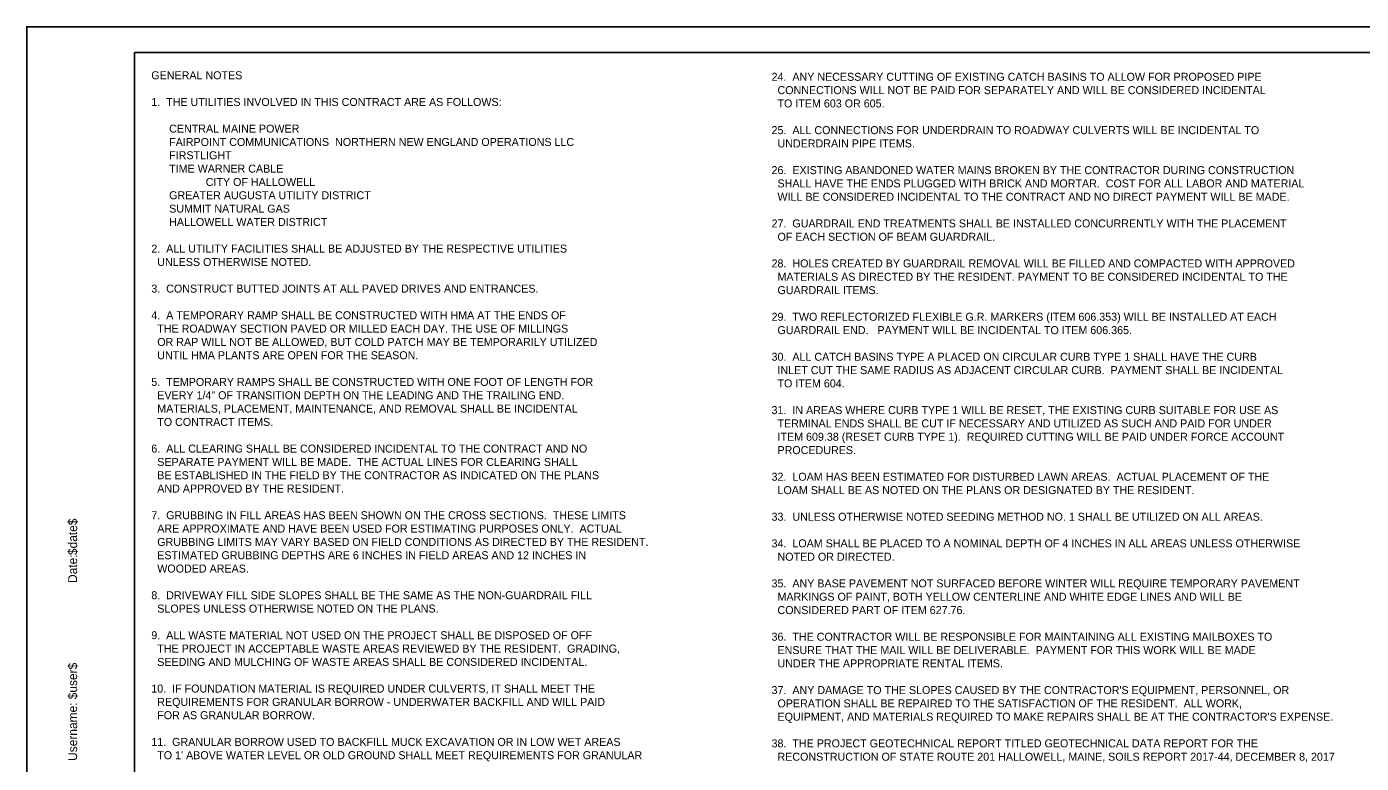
# Model space of a CAD drawing. Extents: x -0.13 to 2.7, y -0.05 to 1.78.
# Drawn here: x -0.135 to 1.533, y 0.861 to 1.782 of the extents above; entities that cross this region are included whole.
import ezdxf

# ---------------------------------------------------------------- set-up
doc = ezdxf.new("R2010")
doc.units = 0
for name, color, linetype in [('ANNOTATION', 7, 'Continuous'), ('BORDER', 7, 'Continuous'), ('PLOT BOUNDARY', 7, 'Continuous')]:
    doc.layers.add(name, color=color, linetype=linetype)

msp = doc.modelspace()

# ---------------------------------------------------------------- linework, layer by layer
at = {"layer": 'BORDER'}
for p, q in [((2.6553, 1.75), (0, 1.75)), ((0, 1.75), (0, 0))]:
    msp.add_line(p, q, dxfattribs=at)
at = {"layer": 'PLOT BOUNDARY'}
msp.add_lwpolyline([(-0.1349, -0.051), (2.6984, -0.051), (2.6984, 1.7823), (-0.1349, 1.7823)], close=True, dxfattribs=at)

# ---------------------------------------------------------------- texts
at = {"layer": 'ANNOTATION'}
for s, p in [('GENERAL NOTES', (0.0208, 1.7166)), ('24.  ANY NECESSARY CUTTING OF EXISTING CATCH BASINS TO ALLOW FOR PROPOSED PIPE ', (0.7957, 1.7147)), ('  CONNECTIONS WILL NOT BE PAID FOR SEPARATELY AND WILL BE CONSIDERED INCIDENTAL ', (0.7957, 1.698)), ('1.  THE UTILITIES INVOLVED IN THIS CONTRACT ARE AS FOLLOWS: ', (0.0208, 1.6832)), ('  TO ITEM 603 OR 605.', (0.7957, 1.6814)), ('      CENTRAL MAINE POWER', (0.0208, 1.6499)), ('25.  ALL CONNECTIONS FOR UNDERDRAIN TO ROADWAY CULVERTS WILL BE INCIDENTAL TO ', (0.7957, 1.648)), ('      FAIRPOINT COMMUNICATIONS  NORTHERN NEW ENGLAND OPERATIONS LLC', (0.0208, 1.6332)), ('  UNDERDRAIN PIPE ITEMS.', (0.7957, 1.6314)), ('      FIRSTLIGHT', (0.0208, 1.6166)), ('      TIME WARNER CABLE', (0.0208, 1.5999)), ('26.  EXISTING ABANDONED WATER MAINS BROKEN BY THE CONTRACTOR DURING CONSTRUCTION ', (0.7957, 1.598)), ('CITY OF HALLOWELL', (0.0888, 1.5832)), ('  SHALL HAVE THE ENDS PLUGGED WITH BRICK AND MORTAR.  COST FOR ALL LABOR AND MATERIAL ', (0.7957, 1.5814)), ('      GREATER AUGUSTA UTILITY DISTRICT', (0.0208, 1.5666)), ('  WILL BE CONSIDERED INCIDENTAL TO THE CONTRACT AND NO DIRECT PAYMENT WILL BE MADE.', (0.7957, 1.5647)), ('      SUMMIT NATURAL GAS', (0.0208, 1.5499)), ('      HALLOWELL WATER DISTRICT', (0.0208, 1.5332)), ('27.  GUARDRAIL END TREATMENTS SHALL BE INSTALLED CONCURRENTLY WITH THE PLACEMENT ', (0.7957, 1.5314)), ('  OF EACH SECTION OF BEAM GUARDRAIL.', (0.7957, 1.5147)), ('2.  ALL UTILITY FACILITIES SHALL BE ADJUSTED BY THE RESPECTIVE UTILITIES ', (0.0208, 1.4999)), ('  UNLESS OTHERWISE NOTED.', (0.0208, 1.4832)), ('28.  HOLES CREATED BY GUARDRAIL REMOVAL WILL BE FILLED AND COMPACTED WITH APPROVED ', (0.7957, 1.4814)), ('  MATERIALS AS DIRECTED BY THE RESIDENT. PAYMENT TO BE CONSIDERED INCIDENTAL TO THE ', (0.7957, 1.4647)), ('3.  CONSTRUCT BUTTED JOINTS AT ALL PAVED DRIVES AND ENTRANCES.', (0.0208, 1.4499)), ('  GUARDRAIL ITEMS.', (0.7957, 1.448)), ('4.  A TEMPORARY RAMP SHALL BE CONSTRUCTED WITH HMA AT THE ENDS OF ', (0.0208, 1.4166)), ('29.  TWO REFLECTORIZED FLEXIBLE G.R. MARKERS (ITEM 606.353) WILL BE INSTALLED AT EACH ', (0.7957, 1.4147)), ('  THE ROADWAY SECTION PAVED OR MILLED EACH DAY. THE USE OF MILLINGS ', (0.0208, 1.3999)), ('  GUARDRAIL END.   PAYMENT WILL BE INCIDENTAL TO ITEM 606.365.', (0.7957, 1.398)), ('  OR RAP WILL NOT BE ALLOWED, BUT COLD PATCH MAY BE TEMPORARILY UTILIZED ', (0.0208, 1.3832)), ('  UNTIL HMA PLANTS ARE OPEN FOR THE SEASON.', (0.0208, 1.3666)), ('30.  ALL CATCH BASINS TYPE A PLACED ON CIRCULAR CURB TYPE 1 SHALL HAVE THE CURB ', (0.7957, 1.3647)), ('  INLET CUT THE SAME RADIUS AS ADJACENT CIRCULAR CURB.  PAYMENT SHALL BE INCIDENTAL ', (0.7957, 1.348)), ('5.  TEMPORARY RAMPS SHALL BE CONSTRUCTED WITH ONE FOOT OF LENGTH FOR ', (0.0208, 1.3332)), ('  TO ITEM 604.', (0.7957, 1.3314)), ('  EVERY 1/4" OF TRANSITION DEPTH ON THE LEADING AND THE TRAILING END. ', (0.0208, 1.3166)), ('  MATERIALS, PLACEMENT, MAINTENANCE, AND REMOVAL SHALL BE INCIDENTAL ', (0.0208, 1.2999)), ('31.  IN AREAS WHERE CURB TYPE 1 WILL BE RESET, THE EXISTING CURB SUITABLE FOR USE AS ', (0.7957, 1.298)), ('  TO CONTRACT ITEMS. ', (0.0208, 1.2832)), ('  TERMINAL ENDS SHALL BE CUT IF NECESSARY AND UTILIZED AS SUCH AND PAID FOR UNDER ', (0.7957, 1.2814)), ('  ITEM 609.38 (RESET CURB TYPE 1).  REQUIRED CUTTING WILL BE PAID UNDER FORCE ACCOUNT ', (0.7957, 1.2647)), ('6.  ALL CLEARING SHALL BE CONSIDERED INCIDENTAL TO THE CONTRACT AND NO ', (0.0208, 1.2499)), ('  PROCEDURES.', (0.7957, 1.248)), ('  SEPARATE PAYMENT WILL BE MADE.  THE ACTUAL LINES FOR CLEARING SHALL ', (0.0208, 1.2332)), ('  BE ESTABLISHED IN THE FIELD BY THE CONTRACTOR AS INDICATED ON THE PLANS ', (0.0208, 1.2166)), ('32.  LOAM HAS BEEN ESTIMATED FOR DISTURBED LAWN AREAS.  ACTUAL PLACEMENT OF THE ', (0.7957, 1.2147)), ('  AND APPROVED BY THE RESIDENT.', (0.0208, 1.1999)), ('  LOAM SHALL BE AS NOTED ON THE PLANS OR DESIGNATED BY THE RESIDENT.', (0.7957, 1.198)), ('7.  GRUBBING IN FILL AREAS HAS BEEN SHOWN ON THE CROSS SECTIONS.  THESE LIMITS ', (0.0208, 1.1666)), ('33.  UNLESS OTHERWISE NOTED SEEDING METHOD NO. 1 SHALL BE UTILIZED ON ALL AREAS. ', (0.7957, 1.1647)), ('  ARE APPROXIMATE AND HAVE BEEN USED FOR ESTIMATING PURPOSES ONLY.  ACTUAL ', (0.0208, 1.1499)), ('  GRUBBING LIMITS MAY VARY BASED ON FIELD CONDITIONS AS DIRECTED BY THE RESIDENT.', (0.0208, 1.1332)), ('34.  LOAM SHALL BE PLACED TO A NOMINAL DEPTH OF 4 INCHES IN ALL AREAS UNLESS OTHERWISE ', (0.7957, 1.1314)), ('  ESTIMATED GRUBBING DEPTHS ARE 6 INCHES IN FIELD AREAS AND 12 INCHES IN ', (0.0208, 1.1166)), ('  NOTED OR DIRECTED.', (0.7957, 1.1147)), ('  WOODED AREAS.', (0.0208, 1.0999)), ('35.  ANY BASE PAVEMENT NOT SURFACED BEFORE WINTER WILL REQUIRE TEMPORARY PAVEMENT', (0.7957, 1.0814)), ('8.  DRIVEWAY FILL SIDE SLOPES SHALL BE THE SAME AS THE NON-GUARDRAIL FILL ', (0.0208, 1.0666)), ('  MARKINGS OF PAINT, BOTH YELLOW CENTERLINE AND WHITE EDGE LINES AND WILL BE ', (0.7957, 1.0647)), ('  SLOPES UNLESS OTHERWISE NOTED ON THE PLANS.', (0.0208, 1.0499)), ('  CONSIDERED PART OF ITEM 627.76.', (0.7957, 1.048)), ('9.  ALL WASTE MATERIAL NOT USED ON THE PROJECT SHALL BE DISPOSED OF OFF ', (0.0208, 1.0166)), ('36.  THE CONTRACTOR WILL BE RESPONSIBLE FOR MAINTAINING ALL EXISTING MAILBOXES TO ', (0.7957, 1.0147)), ('  THE PROJECT IN ACCEPTABLE WASTE AREAS REVIEWED BY THE RESIDENT.  GRADING, ', (0.0208, 0.9999)), ('  ENSURE THAT THE MAIL WILL BE DELIVERABLE.  PAYMENT FOR THIS WORK WILL BE MADE ', (0.7957, 0.998)), ('  SEEDING AND MULCHING OF WASTE AREAS SHALL BE CONSIDERED INCIDENTAL.', (0.0208, 0.9832)), ('  UNDER THE APPROPRIATE RENTAL ITEMS.', (0.7957, 0.9814)), ('10.  IF FOUNDATION MATERIAL IS REQUIRED UNDER CULVERTS, IT SHALL MEET THE ', (0.0208, 0.9499)), ("37.  ANY DAMAGE TO THE SLOPES CAUSED BY THE CONTRACTOR'S EQUIPMENT, PERSONNEL, OR ", (0.7957, 0.948)), ('  REQUIREMENTS FOR GRANULAR BORROW - UNDERWATER BACKFILL AND WILL PAID ', (0.0208, 0.9332)), ('  OPERATION SHALL BE REPAIRED TO THE SATISFACTION OF THE RESIDENT.  ALL WORK, ', (0.7957, 0.9314)), ('  FOR AS GRANULAR BORROW.', (0.0208, 0.9166)), ("  EQUIPMENT, AND MATERIALS REQUIRED TO MAKE REPAIRS SHALL BE AT THE CONTRACTOR'S EXPENSE. ", (0.7957, 0.9147)), ('11.  GRANULAR BORROW USED TO BACKFILL MUCK EXCAVATION OR IN LOW WET AREAS ', (0.0208, 0.8832)), ('38.  THE PROJECT GEOTECHNICAL REPORT TITLED GEOTECHNICAL DATA REPORT FOR THE ', (0.7957, 0.8814)), ("  TO 1' ABOVE WATER LEVEL OR OLD GROUND SHALL MEET REQUIREMENTS FOR GRANULAR ", (0.0208, 0.8666)), ('  RECONSTRUCTION OF STATE ROUTE 201 HALLOWELL, MAINE, SOILS REPORT 2017-44, DECEMBER 8, 2017 ', (0.7957, 0.8647))]:
    msp.add_text(s, height=0.01, dxfattribs=at).set_placement(p)
at = {"layer": 'BORDER'}
for s, p in [('$date$', (-0.0719, 1.1218)), ('Date:', (-0.0719, 1.0869)), ('$user$', (-0.0719, 0.9415)), ('Username:', (-0.0719, 0.8645))]:
    msp.add_text(s, height=0.01116, rotation=90, dxfattribs=at).set_placement(p)

doc.saveas('drawing.dxf')
